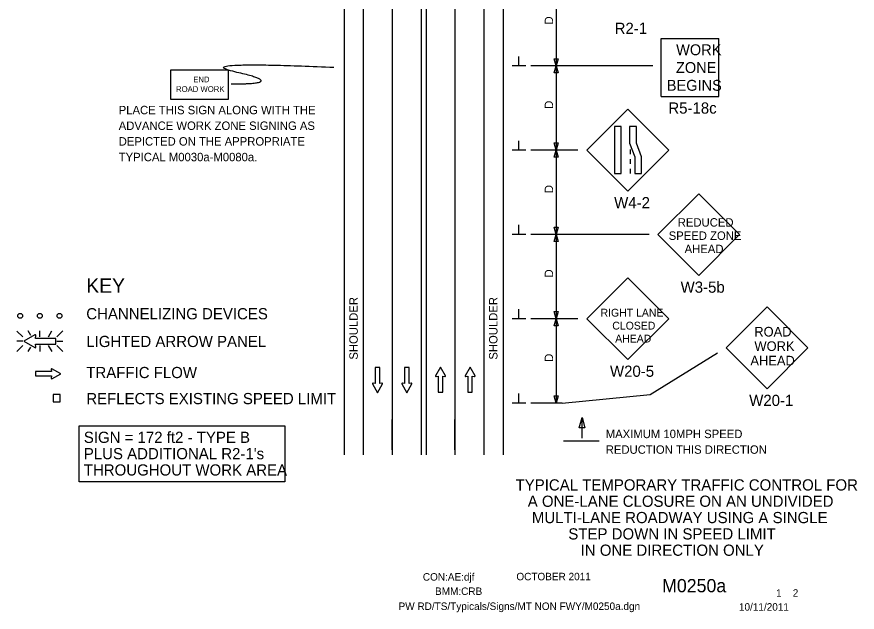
# Model space of a CAD drawing. Extents: x 16747 to 18480, y 5932 to 6927.
# Drawn here: x 16754 to 17451, y 5932 to 6426 of the extents above; entities that cross this region are included whole.
import ezdxf

# ---------------------------------------------------------------- set-up
doc = ezdxf.new("R2010")
doc.units = 0
for name, color, linetype in [('ALI_LEGAL_EX', 7, 'Continuous'), ('BORDER', 7, 'Continuous'), ('BORDER_SIGNAL_WO', 7, 'Continuous'), ('MT_SCRATCH_LEVEL_E', 7, 'Continuous'), ('PAVT_EDGE_EX', 7, 'Continuous'), ('TRAFFIC_SIGNS_PR', 7, 'Continuous'), ('TYPICAL_TEXT_DIMEN_EX', 7, 'Continuous'), ('TYPICAL_TEXT_DIMEN_PR', 7, 'Continuous')]:
    doc.layers.add(name, color=color, linetype=linetype)

msp = doc.modelspace()

# ---------------------------------------------------------------- linework, layer by layer
at = {"layer": 'ALI_LEGAL_EX'}
for p, q in [((17065.33, 6891.74), (17065.33, 6062.55)), ((17117.33, 6891.74), (17117.33, 6062.55))]:
    msp.add_line(p, q, dxfattribs=at)
for points in [[(17065.33, 6391.74), (17065.33, 6366.74)], [(17117.33, 6391.74), (17117.33, 6366.74)], [(17065.33, 6291.74), (17065.33, 6266.74)], [(17117.33, 6291.74), (17117.33, 6266.74)], [(17065.33, 6191.74), (17065.33, 6166.74)], [(17117.33, 6191.74), (17117.33, 6166.74)], [(17065.33, 6066.73), (17065.33, 6091.73)], [(17065.33, 6066.73), (17065.33, 6091.73)], [(17117.33, 6066.73), (17117.33, 6091.73)], [(17117.33, 6066.73), (17117.33, 6091.73)]]:
    msp.add_lwpolyline(points, dxfattribs=at)
at = {"layer": 'MT_SCRATCH_LEVEL_E'}
for p, q in [((17105.3, 6135.37), (17101.19, 6128.13)), ((17105.3, 6135.37), (17101.19, 6128.13)), ((17109.44, 6128.13), (17105.3, 6135.37)), ((17109.44, 6128.13), (17105.3, 6135.37)), ((17129.85, 6135.37), (17125.74, 6128.13)), ((17129.85, 6135.37), (17125.74, 6128.13)), ((17134, 6128.13), (17129.85, 6135.37)), ((17134, 6128.13), (17129.85, 6135.37)), ((16782.67, 6131.69), (16769.41, 6131.69)), ((16769.41, 6131.69), (16769.41, 6127.95)), ((16782.67, 6131.69), (16769.41, 6131.69)), ((16769.41, 6131.69), (16769.41, 6127.95)), ((16782.35, 6133.47), (16782.67, 6131.69)), ((16782.35, 6133.47), (16782.67, 6131.69)), ((16790.28, 6129.84), (16783.03, 6133.95)), ((16790.28, 6129.84), (16783.03, 6133.95)), ((16783.03, 6125.69), (16790.28, 6129.84)), ((16783.03, 6125.69), (16790.28, 6129.84)), ((17055, 6134.91), (17051.26, 6134.91)), ((17051.26, 6134.91), (17051.26, 6121.66)), ((17055, 6134.91), (17051.26, 6134.91)), ((17051.26, 6134.91), (17051.26, 6121.66)), ((17055, 6121.66), (17055, 6134.91)), ((17055, 6121.66), (17055, 6134.91)), ((17079.25, 6134.91), (17075.51, 6134.91)), ((17075.51, 6134.91), (17075.51, 6121.66)), ((17079.25, 6134.91), (17075.51, 6134.91)), ((17075.51, 6134.91), (17075.51, 6121.66)), ((17079.25, 6121.66), (17079.25, 6134.91)), ((17079.25, 6121.66), (17079.25, 6134.91)), ((16769.41, 6127.95), (16782.67, 6127.95)), ((16769.41, 6127.95), (16782.67, 6127.95)), ((16782.67, 6127.95), (16782.35, 6126.17)), ((16782.67, 6127.95), (16782.35, 6126.17)), ((17049, 6121.29), (17053.15, 6114.05)), ((17049, 6121.29), (17053.15, 6114.05)), ((17051.26, 6121.66), (17049.48, 6121.97)), ((17051.26, 6121.66), (17049.48, 6121.97)), ((17053.15, 6114.05), (17057.26, 6121.29)), ((17053.15, 6114.05), (17057.26, 6121.29)), ((17056.78, 6121.97), (17055, 6121.66)), ((17056.78, 6121.97), (17055, 6121.66)), ((17073.26, 6121.29), (17077.4, 6114.05)), ((17073.26, 6121.29), (17077.4, 6114.05)), ((17075.51, 6121.66), (17073.73, 6121.97)), ((17075.51, 6121.66), (17073.73, 6121.97)), ((17077.4, 6114.05), (17081.51, 6121.29)), ((17077.4, 6114.05), (17081.51, 6121.29)), ((17081.03, 6121.97), (17079.25, 6121.66)), ((17081.03, 6121.97), (17079.25, 6121.66)), ((17101.67, 6127.45), (17103.44, 6127.76)), ((17101.67, 6127.45), (17103.44, 6127.76)), ((17103.44, 6127.76), (17103.44, 6114.51)), ((17103.44, 6127.76), (17103.44, 6114.51)), ((17107.19, 6114.51), (17107.19, 6127.76)), ((17107.19, 6127.76), (17108.96, 6127.45)), ((17107.19, 6114.51), (17107.19, 6127.76)), ((17107.19, 6127.76), (17108.96, 6127.45)), ((17126.22, 6127.45), (17128, 6127.76)), ((17126.22, 6127.45), (17128, 6127.76)), ((17128, 6127.76), (17128, 6114.51)), ((17128, 6127.76), (17128, 6114.51)), ((17131.74, 6114.51), (17131.74, 6127.76)), ((17131.74, 6127.76), (17133.52, 6127.45)), ((17131.74, 6114.51), (17131.74, 6127.76)), ((17131.74, 6127.76), (17133.52, 6127.45)), ((17103.44, 6114.51), (17107.19, 6114.51)), ((17103.44, 6114.51), (17107.19, 6114.51)), ((17128, 6114.51), (17131.74, 6114.51)), ((17128, 6114.51), (17131.74, 6114.51))]:
    msp.add_line(p, q, dxfattribs=at)
for centre, start, end in [((16782.81, 6133.54), 60.42484, 189.96381), ((16782.81, 6133.54), 60.42484, 189.96381), ((17101.59, 6127.91), 150.42484, 279.96381), ((17101.59, 6127.91), 150.42484, 279.96381), ((17109.03, 6127.91), 260.03619, 29.77312), ((17109.03, 6127.91), 260.03619, 29.77312), ((17126.15, 6127.91), 150.42484, 279.96381), ((17126.15, 6127.91), 150.42484, 279.96381), ((17133.59, 6127.91), 260.03619, 29.77312), ((17133.59, 6127.91), 260.03619, 29.77312), ((16782.81, 6126.1), 170.03619, 299.77312), ((16782.81, 6126.1), 170.03619, 299.77312), ((17049.41, 6121.51), 80.03619, 209.77312), ((17049.41, 6121.51), 80.03619, 209.77312), ((17056.85, 6121.51), 330.42484, 99.96381), ((17056.85, 6121.51), 330.42484, 99.96381), ((17073.66, 6121.51), 80.03619, 209.77312), ((17073.66, 6121.51), 80.03619, 209.77312), ((17081.11, 6121.51), 330.42484, 99.96381), ((17081.11, 6121.51), 330.42484, 99.96381)]:
    msp.add_arc(centre, 0.463, start, end, dxfattribs=at)
at = {"layer": 'PAVT_EDGE_EX'}
for p, q in [((17025.33, 6926.74), (17025.33, 6062.55)), ((17041.33, 6926.74), (17041.33, 6062.55)), ((17089.33, 6926.74), (17089.33, 6062.55)), ((17093.33, 6926.74), (17093.33, 6062.55)), ((17141.33, 6926.74), (17141.33, 6062.55)), ((17157.33, 6926.74), (17157.33, 6062.55))]:
    msp.add_line(p, q, dxfattribs=at)
at = {"layer": 'TRAFFIC_SIGNS_PR'}
for p, q in [((17288.34, 6360.01), (17288.34, 6408.01)), ((17288.34, 6408.01), (17336.34, 6408.01)), ((17336.34, 6360.01), (17336.34, 6408.01)), ((17288.34, 6360.01), (17336.34, 6360.01)), ((17260.7, 6349.31), (17226.76, 6315.37)), ((17294.65, 6315.37), (17260.7, 6349.31)), ((17226.76, 6315.37), (17260.7, 6281.43)), ((17260.7, 6281.43), (17294.65, 6315.37)), ((17262.76, 6315.99), (17262.76, 6311.99)), ((17262.76, 6307.99), (17262.76, 6303.99)), ((17262.76, 6299.99), (17262.76, 6295.99)), ((17319.59, 6279.22), (17285.64, 6245.28)), ((17353.53, 6245.28), (17319.59, 6279.22)), ((17285.64, 6245.28), (17319.59, 6211.34)), ((17319.59, 6211.34), (17353.53, 6245.28)), ((17260.71, 6209.41), (17226.77, 6175.47)), ((17294.65, 6175.47), (17260.71, 6209.41)), ((17376.22, 6185.21), (17342.28, 6151.27)), ((17410.16, 6151.27), (17376.22, 6185.21)), ((17226.77, 6175.47), (17260.71, 6141.53)), ((17260.71, 6141.53), (17294.65, 6175.47)), ((16753.86, 6165.26), (16758.79, 6160.33)), ((16765.62, 6161.44), (16763.42, 6165.27)), ((16772.94, 6160.33), (16772.94, 6165.27)), ((16780.18, 6160.33), (16783.03, 6165.27)), ((16787.09, 6160.33), (16792.03, 6165.27)), ((16758.79, 6156.78), (16753.86, 6156.78)), ((16787.09, 6156.78), (16792.03, 6156.78)), ((16753.86, 6148.29), (16758.79, 6153.22)), ((16763.37, 6148.28), (16765.48, 6151.95)), ((16772.94, 6153.22), (16772.94, 6148.28)), ((16783.07, 6148.28), (16780.22, 6153.22)), ((16787.09, 6153.22), (16792.03, 6148.28)), ((17342.28, 6151.27), (17376.22, 6117.33)), ((17376.22, 6117.33), (17410.16, 6151.27))]:
    msp.add_line(p, q, dxfattribs=at)
for points in [[(16881.45, 6357.78), (16929.45, 6357.78), (16929.45, 6381.78), (16881.45, 6381.78)], [(17249.59, 6335.04), (17249.59, 6295.99), (17255.2, 6295.99), (17255.2, 6335.04)], [(17262.26, 6335.04), (17262.26, 6321.07), (17266.44, 6309.96), (17266.44, 6295.99), (17272.05, 6295.99), (17272.05, 6309.96), (17267.87, 6321.07), (17267.87, 6335.04)], [(16784.11, 6106.37), (16789.71, 6106.37), (16789.71, 6112.54), (16784.11, 6112.54)]]:
    msp.add_lwpolyline(points, close=True, dxfattribs=at)
for points in [[(16768.87, 6162.05), (16759.58, 6156.78), (16768.87, 6151.45)], [(16769.74, 6152.08), (16769.34, 6154.35), (16786.36, 6154.35), (16786.36, 6159.15), (16769.34, 6159.15), (16769.75, 6161.43)]]:
    msp.add_lwpolyline(points, dxfattribs=at)
for centre in [(16756.65, 6177.89), (16772.95, 6177.89), (16789.25, 6177.89)]:
    msp.add_circle(centre, 2, dxfattribs=at)
for centre, radius, start, end in [((16769.16, 6161.53), 0.598, 350.73078, 118.89165), ((16769.16, 6151.98), 0.597, 241.48329, 9.95933)]:
    msp.add_arc(centre, radius, start, end, dxfattribs=at)
msp.add_open_spline([(16931.67, 6370.33), (16978.9, 6370.33), (16893.88, 6389.68), (17016.98, 6384.19)], degree=2, dxfattribs=at)
at = {"layer": 'TYPICAL_TEXT_DIMEN_EX'}
msp.add_lwpolyline([(16805.73, 6086.6), (16976.09, 6086.6), (16976.09, 6040.04), (16805.73, 6040.04)], close=True, dxfattribs=at)
at = {"layer": 'TYPICAL_TEXT_DIMEN_PR'}
for p, q in [((17201.33, 6455.47), (17201.33, 6385.47)), ((17170.45, 6385.47), (17170.45, 6393.26)), ((17201.33, 6385.47), (17199.76, 6391.33)), ((17199.76, 6391.33), (17201.33, 6391.33)), ((17201.33, 6391.33), (17202.9, 6391.33)), ((17202.9, 6391.33), (17201.33, 6385.47)), ((17176.08, 6385.47), (17164.83, 6385.47)), ((17281.48, 6385.47), (17180.33, 6385.47)), ((17199.76, 6379.61), (17201.33, 6385.47)), ((17201.33, 6379.61), (17199.76, 6379.61)), ((17201.33, 6385.47), (17201.33, 6315.47)), ((17201.33, 6385.47), (17202.9, 6379.61)), ((17202.9, 6379.61), (17201.33, 6379.61)), ((17170.45, 6315.47), (17170.45, 6323.26)), ((17201.33, 6315.47), (17199.76, 6321.33)), ((17199.76, 6321.33), (17201.33, 6321.33)), ((17201.33, 6315.47), (17199.76, 6321.33)), ((17199.76, 6321.33), (17201.33, 6321.33)), ((17201.33, 6321.33), (17202.9, 6321.33)), ((17202.9, 6321.33), (17201.33, 6315.47)), ((17201.33, 6321.33), (17202.9, 6321.33)), ((17202.9, 6321.33), (17201.33, 6315.47)), ((17176.08, 6315.47), (17164.83, 6315.47)), ((17219.33, 6315.47), (17180.33, 6315.47)), ((17199.76, 6309.61), (17201.33, 6315.47)), ((17199.76, 6309.61), (17201.33, 6315.47)), ((17201.33, 6309.61), (17199.76, 6309.61)), ((17201.33, 6309.61), (17199.76, 6309.61)), ((17201.33, 6315.47), (17201.33, 6245.47)), ((17201.33, 6315.47), (17202.9, 6309.61)), ((17201.33, 6315.47), (17202.9, 6309.61)), ((17202.9, 6309.61), (17201.33, 6309.61)), ((17202.9, 6309.61), (17201.33, 6309.61)), ((17170.45, 6245.47), (17170.45, 6253.26)), ((17201.33, 6245.47), (17199.76, 6251.33)), ((17199.76, 6251.33), (17201.33, 6251.33)), ((17201.33, 6251.33), (17202.9, 6251.33)), ((17202.9, 6251.33), (17201.33, 6245.47)), ((17176.08, 6245.47), (17164.83, 6245.47)), ((17278.39, 6245.47), (17180.33, 6245.47)), ((17199.76, 6239.61), (17201.33, 6245.47)), ((17199.76, 6239.61), (17201.33, 6245.47)), ((17201.33, 6245.47), (17201.33, 6175.47)), ((17201.33, 6245.47), (17202.9, 6239.61)), ((17201.33, 6245.47), (17202.9, 6239.61)), ((17201.33, 6239.61), (17199.76, 6239.61)), ((17201.33, 6239.61), (17199.76, 6239.61)), ((17202.9, 6239.61), (17201.33, 6239.61)), ((17202.9, 6239.61), (17201.33, 6239.61)), ((17170.45, 6175.47), (17170.45, 6183.26)), ((17201.33, 6175.47), (17199.76, 6181.33)), ((17199.76, 6181.33), (17201.33, 6181.33)), ((17201.33, 6175.47), (17199.76, 6181.33)), ((17199.76, 6181.33), (17201.33, 6181.33)), ((17201.33, 6181.33), (17202.9, 6181.33)), ((17202.9, 6181.33), (17201.33, 6175.47)), ((17201.33, 6181.33), (17202.9, 6181.33)), ((17202.9, 6181.33), (17201.33, 6175.47)), ((17176.08, 6175.47), (17164.83, 6175.47)), ((17219.33, 6175.47), (17180.33, 6175.47)), ((17199.76, 6169.61), (17201.33, 6175.47)), ((17201.33, 6175.47), (17201.33, 6105.47)), ((17201.33, 6175.47), (17202.9, 6169.61)), ((17201.33, 6169.61), (17199.76, 6169.61)), ((17202.9, 6169.61), (17201.33, 6169.61)), ((17279.37, 6112.64), (17335.07, 6147.26)), ((17170.45, 6105.47), (17170.45, 6113.26)), ((17201.33, 6105.47), (17199.76, 6111.33)), ((17199.76, 6111.33), (17201.33, 6111.33)), ((17201.33, 6111.33), (17202.9, 6111.33)), ((17202.9, 6111.33), (17201.33, 6105.47)), ((17206.33, 6105.47), (17279.37, 6112.64)), ((17176.08, 6105.47), (17164.83, 6105.47)), ((17206.33, 6105.47), (17180.33, 6105.47)), ((17220.38, 6084.76), (17222.74, 6093.55)), ((17222.74, 6076.43), (17222.74, 6093.55)), ((17222.74, 6093.55), (17225.09, 6084.76)), ((17222.74, 6084.76), (17220.38, 6084.76)), ((17225.09, 6084.76), (17222.74, 6084.76)), ((17236.91, 6073.93), (17207.47, 6073.93))]:
    msp.add_line(p, q, dxfattribs=at)

# ---------------------------------------------------------------- texts
at = {"layer": 'BORDER'}
for s, p in [('TYPICAL TEMPORARY TRAFFIC CONTROL FOR', (17167.63, 6032.86)), ('A ONE-LANE CLOSURE ON AN UNDIVIDED', (17177.73, 6019.31)), ('MULTI-LANE ROADWAY USING A SINGLE', (17181.15, 6005.76)), ('STEP DOWN IN SPEED LIMIT', (17211.39, 5992.21)), ('IN ONE DIRECTION ONLY', (17221.59, 5978.66))]:
    msp.add_text(s, height=9.3, dxfattribs=at).set_placement(p)
at = {"layer": 'BORDER_SIGNAL_WO'}
for s, height, p in [('CON:AE:djf', 6.2, (17090.69, 5958.06)), ('    OCTOBER 2011    ', 6.2, (17159.08, 5958.34)), ('    M0250a   ', 11, (17272.86, 5948.38)), ('BMM:CRB   ', 6.2, (17100.81, 5946.17)), (' 1    2 ', 6.2, (17381.45, 5944.7)), ('PW RD/TS/Typicals/Signs/MT NON FWY/M0250a.dgn    ', 6.2, (17070.55, 5933.71)), ('10/11/2011    ', 6.2, (17352.93, 5933.13))]:
    msp.add_text(s, height=height, dxfattribs=at).set_placement(p)
at = {"layer": 'TRAFFIC_SIGNS_PR'}
for s, height, p in [('R2-1', 9.3, (17249.79, 6411.87)), ('WORK', 9.021, (17300.84, 6394.22)), ('ZONE', 9.021, (17300.69, 6379.45)), ('END', 4.789, (16900.2, 6371.69)), ('BEGINS', 9.021, (17293.1, 6364.69)), ('ROAD WORK', 4.789, (16885.96, 6363.71)), ('PLACE THIS SIGN ALONG WITH THE', 7, (16838.39, 6345.17)), ('R5-18c', 9.3, (17294.36, 6345.71)), ('ADVANCE WORK ZONE SIGNING AS', 7, (16838.39, 6332.17)), ('DEPICTED ON THE APPROPRIATE', 7, (16838.39, 6319.17)), ('TYPICAL M0030a-M0080a.', 7, (16838.39, 6306.17)), ('W4-2', 9.3, (17249.4, 6267.13)), ('REDUCED', 7, (17302.16, 6251.91)), ('SPEED ZONE', 7, (17294.65, 6240.91)), ('AHEAD', 7, (17307.85, 6229.91)), ('W3-5b', 9.3, (17304.53, 6197.04)), ('RIGHT LANE', 6.5, (17238.11, 6177.22)), ('CLOSED', 6.5, (17247.85, 6166.47)), ('ROAD', 8, (17365.65, 6160.69)), ('AHEAD', 6.5, (17250.28, 6155.72)), ('WORK', 8, (17365.78, 6148.69)), ('AHEAD', 8, (17362.42, 6136.69)), ('W20-5', 9.3, (17245.93, 6127.23)), ('W20-1', 9.3, (17361.43, 6103.03))]:
    msp.add_text(s, height=height, dxfattribs=at).set_placement(p)
at = {"layer": 'TYPICAL_TEXT_DIMEN_EX'}
for s, height, p in [('KEY', 12, (16811.49, 6197)), ('CHANNELIZING DEVICES', 9.3, (16811.49, 6174.95)), ('LIGHTED ARROW PANEL', 9.3, (16811.49, 6151.95)), ('TRAFFIC FLOW', 9.3, (16811.49, 6126.15)), ('REFLECTS EXISTING SPEED LIMIT', 9.3, (16811.49, 6104.53)), ('SIGN = 172 ft2 - TYPE B', 9.3, (16809.45, 6072.36)), ("PLUS ADDITIONAL R2-1's", 9.3, (16809.45, 6058.81)), ('THROUGHOUT WORK AREA', 9.3, (16809.45, 6045.26))]:
    msp.add_text(s, height=height, dxfattribs=at).set_placement(p)
at = {"layer": 'TYPICAL_TEXT_DIMEN_PR'}
for s, p in [('D', (17198.77, 6419.69)), ('D', (17198.77, 6349.69)), ('D', (17198.77, 6349.69)), ('D', (17198.77, 6279.69)), ('D', (17198.77, 6209.69)), ('SHOULDER', (17036.71, 6141.48)), ('SHOULDER', (17152.61, 6141.48)), ('D', (17198.77, 6139.69))]:
    msp.add_text(s, height=7, rotation=90, dxfattribs=at).set_placement(p)
for s, p in [('MAXIMUM 10MPH SPEED', (17242.43, 6076.35)), ('REDUCTION THIS DIRECTION', (17242.43, 6063.35))]:
    msp.add_text(s, height=7, dxfattribs=at).set_placement(p)

doc.saveas('drawing.dxf')
